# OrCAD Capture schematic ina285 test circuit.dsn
size A; title: INA285 High-Accuracy Current Shunt Monitor, Zero-Drift Series; rev: 1.0; note: Datasheet:SBOS485
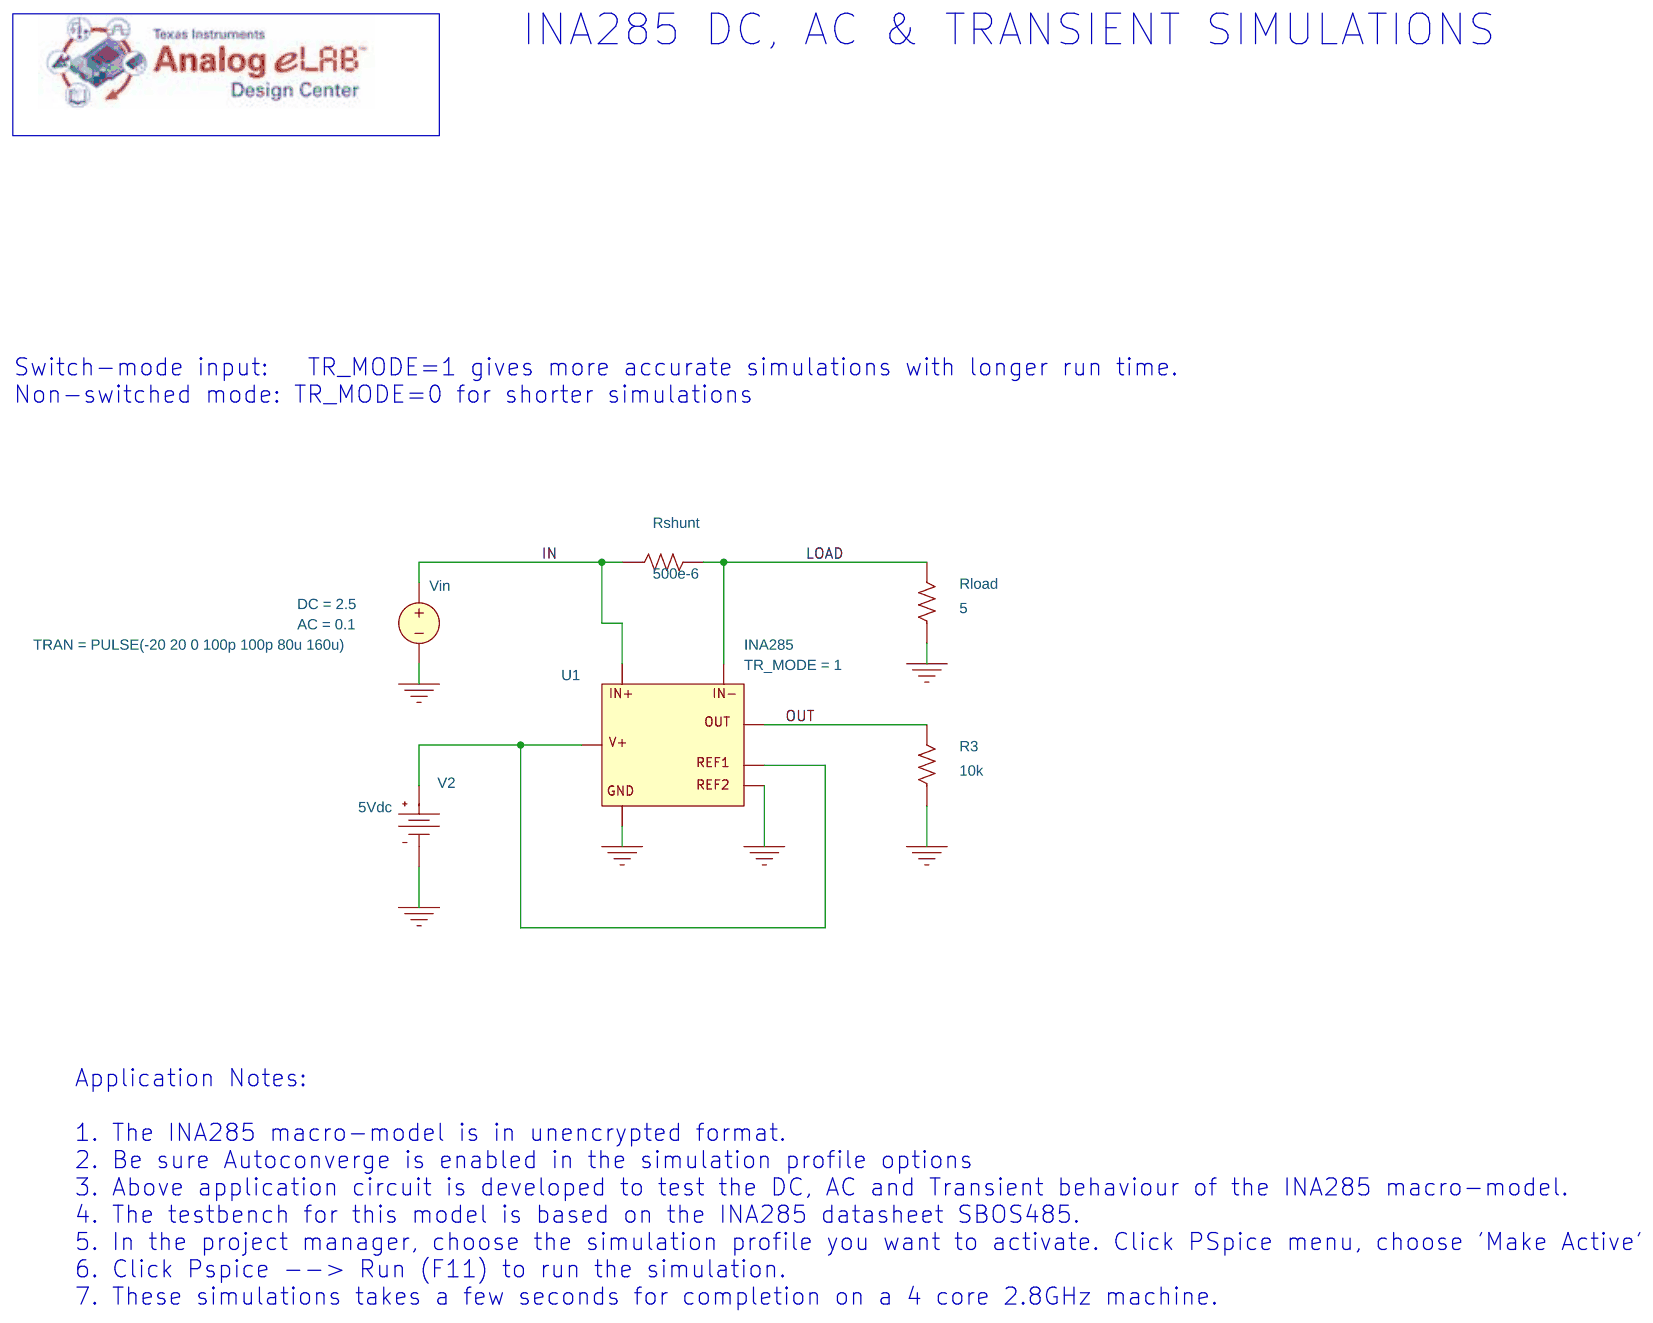
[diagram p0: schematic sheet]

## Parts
R3  10k  [AX/RC05]
Rload  5  [AX/RC05]
Rshunt  500e-6  [AX/RC05]
U1  INA285
V2  VDC
Vin  VSRC

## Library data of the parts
R3 Rload Rshunt = R
U1 = INA285: TR_MODE: 1
V2 = VDC: DC: 5Vdc
Vin = VSRC: AC: 0.1; DC: 2.5; TRAN: PULSE(-20 20 0 100p 100p 80u 160u)

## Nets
0: R3.1 Rload.1 U1.4(GND) U1.7(REF2) V2.1(-) Vin.1(-)
IN: Rshunt.1 U1.1(IN+) Vin.0(+)
LOAD: Rload.2 Rshunt.2 U1.2(IN-)
OUT: R3.2 U1.5(OUT)
N14290888: U1.3(V+) U1.6(REF1) V2.0(+)

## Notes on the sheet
- INA285 DC, AC & TRANSIENT SIMULATIONS
- Switch-mode input:   TR_MODE=1 gives more accurate simulations with longer run time.
  Non-switched mode: TR_MODE=0 for shorter simulations
- Application Notes:
  1. The INA285 macro-model is in unencrypted format.
  2. Be sure Autoconverge is enabled in the simulation profile options
  3. Above application circuit is developed to test the DC, AC and Transient behaviour of the INA285 macro-model.
  4. The testbench for this model is based on the INA285 datasheet SBOS485.
  5. In the project manager, choose the simulation profile you want to activate. Click PSpice menu, choose 'Make Active'
  6. Click Pspice --> Run (F11) to run the simulation.
  7. These simulations takes a few seconds for completion on a 4 core 2.8GHz machine.
